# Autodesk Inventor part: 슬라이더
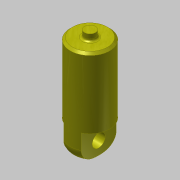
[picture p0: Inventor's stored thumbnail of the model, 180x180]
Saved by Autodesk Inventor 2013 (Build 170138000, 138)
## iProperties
Created: 2016-08
Part Number: 슬라이더
Material: 강철, 탄소
Document SubType Name: Modeling
Designer: mduedu
Density: 7.87 g/cm^3
Author: mduedu
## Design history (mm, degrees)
sketch "스케치1"
  geometry: C1 r 9 at (0, 0); 1 further point
  constraints: 1 centre point, 1 coincident
  dimensions: "d0" = 18 diameter of C1
extrude "돌출1" new body sketch "스케치1" distance "d1" = 45; taper "d2" = 0 deg
fillet "모깎기1" dims "d21" = 6
sketch "스케치6"
  geometry: L1 (9, 6)-(9, 45) reference; L2 (-9, 6)-(-9, 45) reference; L3 (9, 45)-(-9, 45) reference; L4 (0, 45)-(0, 0); L5 (9, 13)-(4, 13); L6 (4, 13)-(4, 0); L7 (4, 0)-(9, 0); L8 (9, 0)-(9, 13); L9 (-9, 13)-(-4, 13); L10 (-4, 13)-(-4, 0); L11 (-4, 0)-(-9, 0); L12 (-9, 0)-(-9, 13)
  constraints: 18 end point, 4 symmetric about line, 2 parallel, 2 perpendicular, 1 horizontal, 1 horizontal alignment, 1 midpoint, 1 point on line
  dimensions: "d22" = 13 distance of L7.end L5.start; "d24" = 4 distance between parallel lines of L6 L4
extrude "돌출5" cut sketch "스케치6" stored distance "d25" = 8; taper "d26" = 0 deg
sketch "스케치8"
  geometry: C1 r 3 at (6, 0); 1 further point
  constraints: 1 centre point, 1 horizontal alignment
  dimensions: "d27" = 6 diameter of C1; "d28" = 6 distance of point (0, 0) C1.centre
extrude "돌출6" cut sketch "스케치8" stored distance "d29" = 8; taper "d30" = 0 deg
chamfer "모따기2" distance "d43" = 1; stored, may be unused: second distance "d44" = 2, angle "d45" = 30 deg
sketch "스케치9"
  geometry: C1 r 2.5 at (0, 0); 1 further point
  constraints: 1 centre point, 1 coincident
  dimensions: "d47" = 5 diameter of C1
extrude "돌출7" join sketch "스케치9" distance "d48" = 3; taper "d49" = 0 deg
fillet "모깎기2" dims "d50" = 1
node "솔리드1"
